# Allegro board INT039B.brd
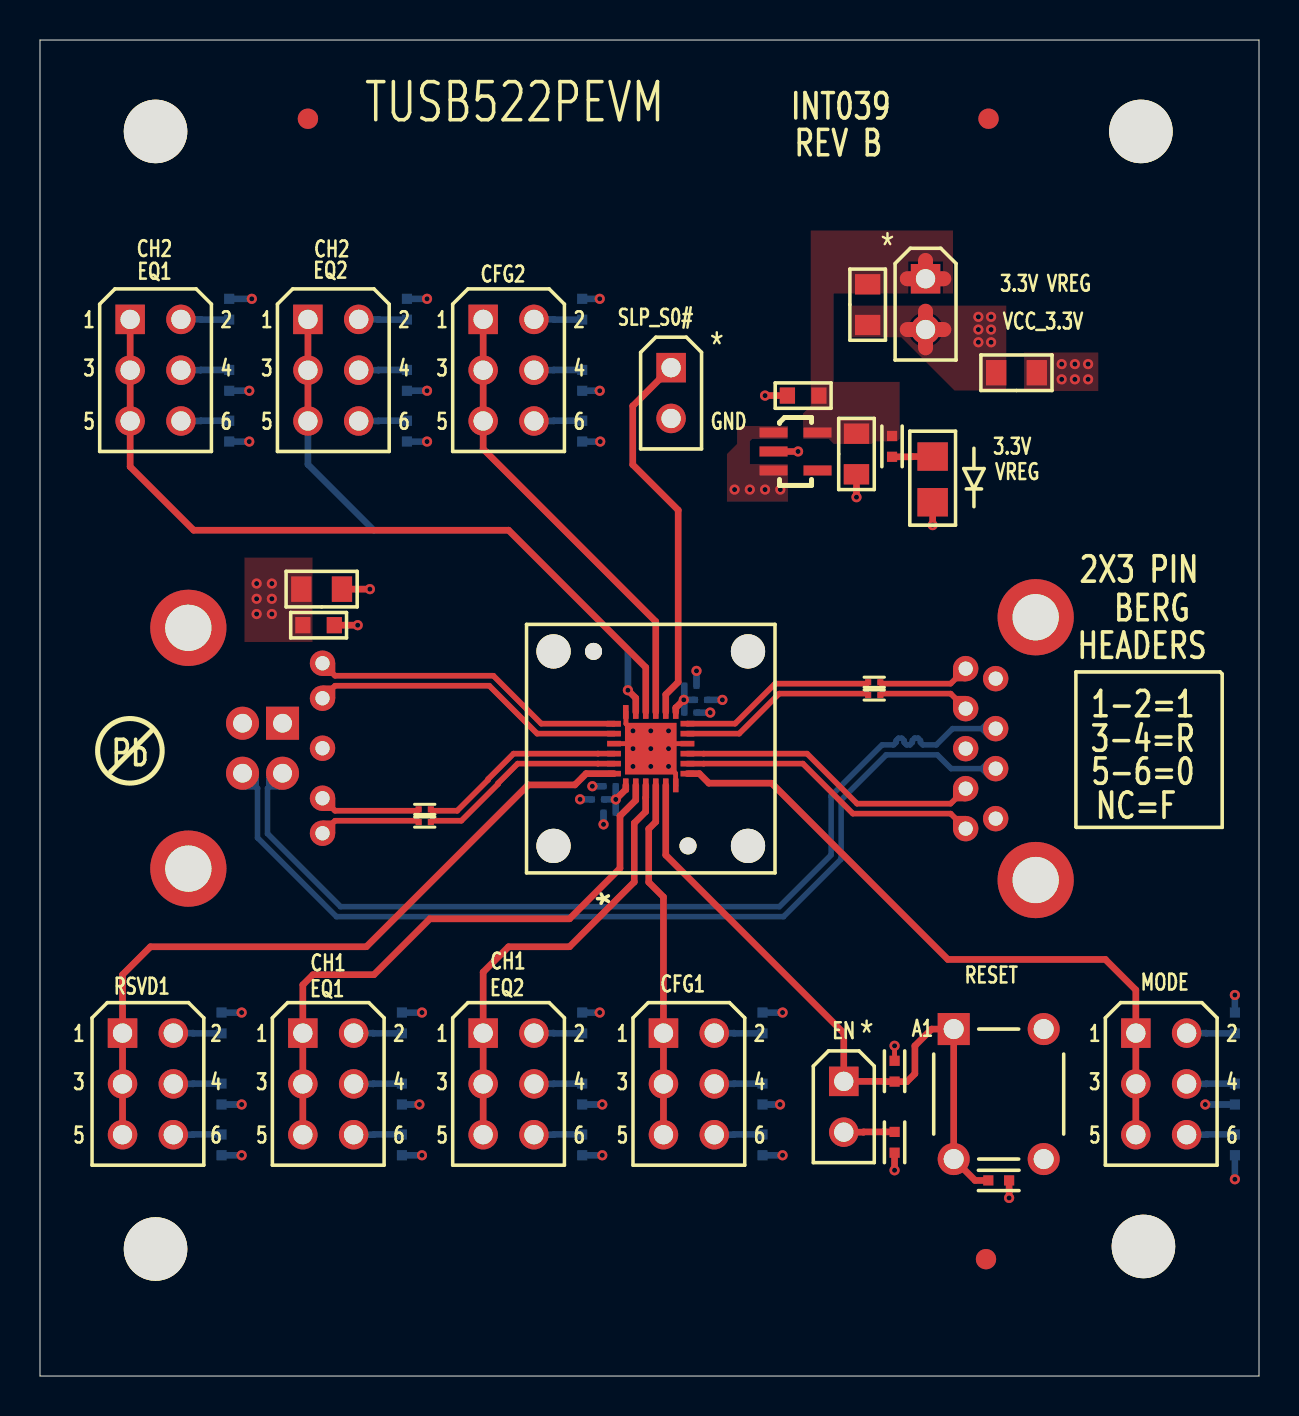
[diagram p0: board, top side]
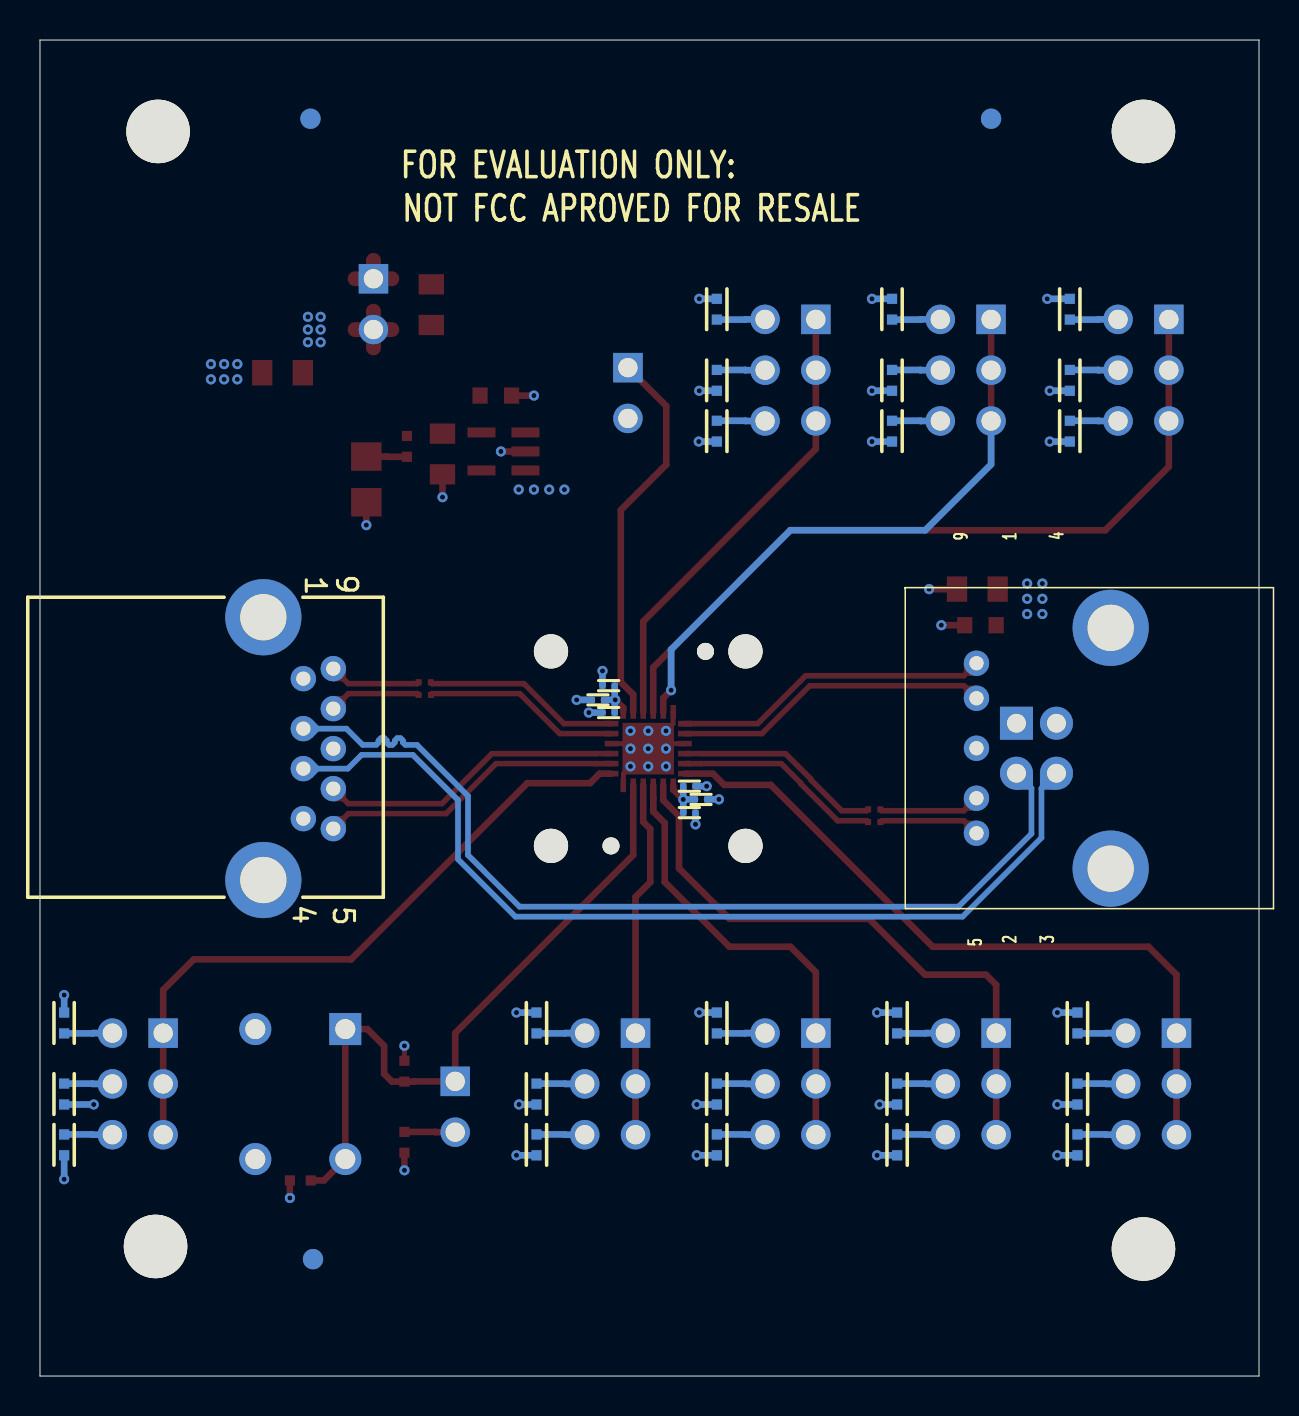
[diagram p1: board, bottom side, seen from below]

Outline 60.96 x 66.8 mm; copper layers: TOP, L2_GND, L3_PWR, BOTTOM. Coordinates in mm from the lower left corner of the outline.
Outline path: 0,66.8 60.96,66.8 60.96,0 0,0 0,66.8

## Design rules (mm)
net group DIFFPAIR0: nets TX1N_CONN TX1P_CONN
net group DIFFPAIR1: nets RX2N RX2P
net group DIFFPAIR2: nets USB2_DM USB2_DP
net group DIFFPAIR3: nets RX1N RX1P
net group DIFFPAIR4: nets TX2N_CONN TX2P_CONN
net group DIFFPAIR5: nets TX1N TX1P
net group DIFFPAIR6: nets TX2N TX2P

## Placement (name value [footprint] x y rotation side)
C1  0.1uF  [0201]  19.24 28.33 0 top
C2  0.1uF  [0201]  19.24 27.7 0 top
C3  0.1uF  [0201]  41.72 34.69 0 top
C4  0.1uF  [0201]  41.72 34.05 0 top
C5  10uF  [0805]  14.08 39.34 0 top
C6  10uF  [0805]  40.83 46.1 270 top
C7  1uf  [0603]  13.93 37.54 0 top
C8  1uf  [0603]  38.16 49.02 180 top
C9  1uF  [0201]  28.49 29.49 180 bottom
C10  1uF  [0201]  32.52 33.17 0 bottom
C11  0.1uF  [0201]  27.9 28.83 180 bottom
C12  0.1uF  [0201]  33.06 33.81 0 bottom
C13  0.01uF  [0201]  28.49 28.17 180 bottom
C14  0.01uF  [0201]  32.52 34.52 0 bottom
C15  22uF  [0805]  48.83 50.16 0 top
C16  200nF  [0402]  47.94 9.78 0 top
D1  LED Green 0805  [LED_0805]  44.64 44.83 90 top
J1  HDR3X2 .1X.1  [HDR_THVT_2X3_100]  13.14 17.14 0 top
J2  HDR3X2 .1X.1  [HDR_THVT_2X3_100]  22.16 17.14 0 top
J3  HDR3X2 .1X.1  [HDR_THVT_2X3_100]  4.51 52.83 0 top
J4  HDR3X2 .1X.1  [HDR_THVT_2X3_100]  13.4 52.83 0 top
J5  HDR3X2 .1X.1  [HDR_THVT_2X3_100]  31.18 17.14 0 top
J6  HDR3X2 .1X.1  [HDR_THVT_2X3_100]  4.13 17.14 0 top
J7  HDR3X2 .1X.1  [HDR_THVT_2X3_100]  54.8 17.14 0 top
J8  HDR3X2 .1X.1  [HDR_THVT_2X3_100]  22.16 52.83 0 top
J9  HDR2X1 M .1  [HDR_THVT_1X2_100]  40.2 14.73 0 top
J10  HDR2X1 M .1  [HDR_THVT_1X2_100]  31.56 50.42 0 top
J11  HDR2X1 M .1  [HDR_THVT_1X2_100]  44.28 54.86 0 top
NOREF  -  []  88.33 38.1 0 top
NOREF#2  -  []  12.05 0.86 0 top
NOREF#3  -  [unnamed#2]  55.18 6.48 0 top
NOREF#4  -  [unnamed#2]  5.78 6.35 0 top
NOREF#5  -  []  -0.57 0 0 top
NOREF#6  -  [unnamed#2]  13.4 62.87 0 top
NOREF#7  -  [unnamed#2]  47.43 62.87 0 top
NOREF#8  -  [unnamed#2]  55.05 62.23 0 top
NOREF#9  -  []  60.96 0 90 top
NOREF#10  -  []  -4.38 -69.85 0 top
NOREF#11  -  []  0 66.8 0 top
NOREF#12  -  [unnamed#2]  47.31 5.84 0 top
NOREF#13  -  [unnamed#2]  5.78 62.23 0 top
NOREF#14  -  []  29.92 5.29 180 bottom
NOREF#15  -  [unnamed#2]  47.43 62.87 180 bottom
NOREF#16  -  [unnamed#2]  47.31 5.84 180 bottom
NOREF#17  -  [unnamed#2]  13.4 62.87 180 bottom
P1  USB3.0 Type B Receptacle  [USB3_TYPEB_AK4AA009]  12.13 32.64 90 bottom
P2  USB3 Type A Receptacle  [USB3_TYPEA]  46.29 31.37 270 bottom
R1  1k  [0402]  18.1 17.65 90 bottom
R2  20k  [0402]  18.1 14.1 270 bottom
R3  1k  [0402]  18.1 11.56 270 bottom
R4  1k  [0402]  27.11 17.65 90 bottom
R5  20k  [0402]  27.11 14.1 270 bottom
R6  1k  [0402]  27.11 11.56 270 bottom
R7  1k  [0402]  9.46 53.34 90 bottom
R8  20k  [0402]  9.46 49.78 270 bottom
R9  1k  [0402]  9.46 47.24 270 bottom
R10  1k  [0402]  18.35 53.34 90 bottom
R11  20k  [0402]  18.35 49.78 270 bottom
R12  1k  [0402]  18.35 47.24 270 bottom
R13  1k  [0402]  36.13 17.65 90 bottom
R14  20k  [0402]  36.13 14.1 270 bottom
R15  1k  [0402]  36.13 11.56 270 bottom
R16  1k  [0402]  9.08 17.65 90 bottom
R17  20k  [0402]  9.08 14.1 270 bottom
R18  1k  [0402]  9.08 11.56 270 bottom
R19  1k  [0402]  59.75 17.65 90 bottom
R20  20k  [0402]  59.75 14.1 270 bottom
R21  1k  [0402]  59.75 11.56 270 bottom
R22  1k  [0402]  27.11 53.34 90 bottom
R23  20k  [0402]  27.11 49.78 270 bottom
R24  1k  [0402]  27.11 47.24 270 bottom
R25  1k  [0402]  42.74 11.68 270 top
R26  0 Ohm  [0805]  41.39 53.57 270 top
R27  10k - NO POP  [0402]  42.74 15.24 270 top
R28  300 Ohm  [0402]  42.61 46.48 270 top
SW1  Switch - Push Button  [SW_THVT_EVQPAX05]  47.94 14.1 0 top
U1  TUSB1002RGE  [SKT_TUSB1002RGE]  30.54 31.37 90 top
U2  LP5907  [DBV_R-PDSO-G5]  37.78 46.23 0 top

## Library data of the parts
C1-C4 C9-C14 = cc0201
C5 C6 C15 = cc0805
C7 C8 = cc0603 1.0uf 25V
C16 = cc0402
D1 = LED Green 0805_0
J1-J8 = HDR3X2 M .1X.1
J9-J11 = HDR2X1 M .1
P1 = USB 3.0 Type B Receptacle
P2 = USB 3.0 Type A Receptacle
R1-R25 R27 R28 = r0402
R26 = r0805
SW1 = Switch - Push Button_0
U1 = TUSB1002RGE
U2 = LP5907

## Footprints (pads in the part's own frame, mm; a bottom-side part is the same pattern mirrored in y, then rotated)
0201
  rect 0.305x0.305 smd: 1(-0.305,0) 2(0.305,0)
0402
  rect 0.508x0.508 smd: 1(-0.521,0) 2(0.521,0)
0603
  rect 0.762x0.813 smd: 1(-0.787,0) 2(0.787,0)
0805
  rect 1.016x1.27 smd: 1(-1.016,0) 2(1.016,0)
DBV_R-PDSO-G5
  rect 1.4x0.5 smd: 1(-1.1,0.95) 2(-1.1,0) 3(-1.1,-0.95) 4(1.1,-0.95) 5(1.1,0.95)
HDR_THVT_1X2_100
  rect 1.473x1.473 hole 0.965: 1(0,0)
  round 1.473 hole 0.965: 2(0,-2.54)
HDR_THVT_2X3_100
  rect 1.473x1.473 hole 0.965: 1(0,0)
  round 1.473 hole 0.965: 2(2.54,0) 3(0,-2.54) 4(2.54,-2.54) 5(0,-5.08) 6(2.54,-5.08)
LED_0805
  rect 1.422x1.524 smd: 1(-1.143,0) 2(1.143,0)
SKT_TUSB1002RGE
  round 1.71 hole 1.71 unplated: (-4.863,4.863) (-4.863,-4.863) (4.863,4.863) (4.863,-4.863)
  round 0.85 hole 0.85 unplated: (-4.863,-1.863) (4.863,2.863)
  rect 0.69x0.28 smd: 1(-1.835,1.25) 2(-1.835,0.75) 3(-1.835,0.25) 4(-1.835,-0.25) 5(-1.835,-0.75) 6(-1.835,-1.25) 13(1.835,-1.25) 14(1.835,-0.75) 15(1.835,-0.25) 16(1.835,0.25) 17(1.835,0.75) 18(1.835,1.25)
  rect 0.28x0.69 smd: 7(-1.25,-1.835) 8(-0.75,-1.835) 9(-0.25,-1.835) 10(0.25,-1.835) 11(0.75,-1.835) 12(1.25,-1.835) 19(1.25,1.835) 20(0.75,1.835) 21(0.25,1.835) 22(-0.25,1.835) 23(-0.75,1.835) 24(-1.25,1.835)
  rect 2.58x2.58 smd: 25(0,0)
SW_THVT_EVQPAX05
  rect 1.6x1.6 hole 1: A1(-2.25,3.25)
  round 1.6 hole 1: A2(-2.25,-3.25) B1(2.25,3.25) B2(2.25,-3.25)
unnamed#2
  round 3.175 hole 3.175 unplated: (0,0)
USB3_TYPEA
  round 1.27 hole 0.711: 1(-3.5,-1.5) 2(-1,-1.5) 3(1,-1.5) 4(3.5,-1.5) 5(4,0) 6(2,0) 7(0,0) 8(-2,0) 9(-4,0)
  round 3.81 hole 2.311: 10(-6.57,-3.5) 11(6.57,-3.5)
USB3_TYPEB_AK4AA009
  rect 1.651x1.651 hole 0.94: 1(0,0)
  round 1.651 hole 0.94: 2(-2.5,0) 3(-2.5,-2) 4(0,-2)
  round 1.27 hole 0.711: 5(-5.5,2) 6(-3.75,2) 7(-1.25,2) 8(1.25,2) 9(3,2)
  round 3.81 hole 2.311: 10(-7.27,-4.71) 11(4.77,-4.71)

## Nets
3.3V: C6.1 C8.1 J11.1 R26.1 R28.1 U2.5(VOUT)
GND: C5.2 C6.2 C7.2 C8.2 C9.2 C10.2 C11.2 C12.2 C13.2 C14.2 C15.2 C16.2 D1.1(CATHODE) J10.2 P1.4(GND) P1.7(GND_DRAIN) P1.10(SHIELD1) P1.11(SHIELD2) P2.4(GND) P2.7(GND_DRAIN) P2.10(SHIELD1) P2.11(SHIELD2) R2.2 R3.2 R5.2 R6.2 R8.2 R9.2 R11.2 R12.2 R14.2 R15.2 R17.2 R18.2 R20.2 R21.2 R23.2 R24.2 R25.2 SW1.B1 SW1.B2 U1.6(GND#6) U1.10(GND#10) U1.18(GND#18) U1.21(GND#21) U1.25(PAD) U2.2(GND)
VBUS: C5.1 C7.1 P1.1(VBUS) P2.1(VBUS) U2.1(VIN) U2.3(EN)
VCC_3.3V: C9.1 C10.1 C11.1 C12.1 C13.1 C14.1 C15.1 J11.2 R1.2 R4.2 R7.2 R10.2 R13.2 R16.2 R19.2 R22.2 R26.2 R27.1 U1.1(VCC#1) U1.13(VCC#13)
CH1_CFG1: J1.1 J1.3 J1.5 U1.2(CH1_CFG1)
CH1_CFG2: J2.1 J2.3 J2.5 U1.3(CH1_CFG2)
CH2_CFG1: J3.1 J3.3 J3.5 U1.16(CH2_CFG1)
CH2_CFG2: J4.1 J4.3 J4.5 U1.17(CH2_CFG2)
EN_RXD: C16.1 J9.1 R27.2 SW1.A1 SW1.A2 U1.5(EN_RXD)
RSVD1: J10.1 U1.14(RSVD1)
RX1N: P2.5(SS_RX_N) U1.8(RX1N)
RX1P: P2.6(SS_RX_P) U1.9(RX1P)
RX2N: P1.8(SS_RX_N) U1.20(RX2N)
RX2P: P1.9(SS_RX_P) U1.19(RX2P)
SQL_CFG: J8.1 J8.3 J8.5 U1.15(SQL_CFG)
TEST1: J5.1 J5.3 J5.5 U1.4(TEST1)
TEST2: J7.1 J7.3 J7.5 U1.7(TEST2)
TEST3: J6.1 J6.3 J6.5 U1.24(TEST3)
TX1N: C2.2 U1.23(TX1N)
TX1N_CONN: C2.1 P1.5(SS_TX_N)
TX1P: C1.2 U1.22(TX1P)
TX1P_CONN: C1.1 P1.6(SS_TX_P)
TX2N: C4.1 U1.11(TX2N)
TX2N_CONN: C4.2 P2.8(SS_TX_N)
TX2P: C3.1 U1.12(TX2P)
TX2P_CONN: C3.2 P2.9(SS_TX_P)
USB2_DM: P1.2(USB2_DM) P2.2(USB2_DM)
USB2_DP: P1.3(USB2_DP) P2.3(USB2_DP)
N04057: J1.2 R1.1
N04069: J1.4 R2.1
N04073: J1.6 R3.1
N04156: J2.2 R4.1
N04168: J2.4 R5.1
N04172: J2.6 R6.1
N04339: J3.2 R7.1
N04351: J3.4 R8.1
N04355: J3.6 R9.1
N04442: J4.2 R10.1
N04460: J4.4 R11.1
N04464: J4.6 R12.1
N04816: J5.2 R13.1
N04828: J5.4 R14.1
N04832: J5.6 R15.1
N05035: J7.2 R19.1
N05047: J7.4 R20.1
N05051: J7.6 R21.1
N05588: J6.2 R16.1
N05600: J6.4 R17.1
N05604: J6.6 R18.1
N05749: J8.2 R22.1
N05761: J8.4 R23.1
N05765: J8.6 R24.1
N05896: J9.2 R25.1
N16532433: D1.2(ANNODE) R28.2

Pads without a net: U2 4

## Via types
v1: diameter 0.508, hole 0.254, TOP to BOTTOM, 73 vias

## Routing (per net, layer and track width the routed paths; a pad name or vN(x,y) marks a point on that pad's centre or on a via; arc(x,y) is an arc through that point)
3.3V: length 2.7
  TOP w0.749: J11.1 45.2,54.86 ; J11.1 43.37,54.86 ; J11.1 44.28,55.78
GND: length 94.1
  TOP w0.241: 30.29,31.62 v1(30.54,31.37) ; 30.29,31.62 v1(29.65,32.26) 29.3,32.61 29.3,33.2 U1.18 ; 30.29,31.62 U1.21 ; v1(30.54,31.37) v1(31.43,30.48) 31.79,30.13 31.79,29.54 U1.6 ; v1(30.54,31.37) 30.79,31.62 U1.10
  TOP w0.33: C8.2 v1(36.26,49.02) ; C6.2 v1(40.83,43.94) ; R25.2 v1(42.74,10.29) ; U2.2 v1(37.91,46.23) ; C5.2 v1(16.5,39.34) ; C16.2 v1(48.46,8.9) ; C7.2 v1(15.89,37.54) ; D1.1 v1(44.64,42.55)
  L2_GND w0.241: SW1.B1 50.19,18.33 ; SW1.B1 49.21,17.35 ; SW1.B1 50.19,16.37 ; SW1.B1 51.17,17.35 ; 49.21,10.85 SW1.B2 ; SW1.B2 50.19,9.87 ; SW1.B2 50.19,11.83 ; SW1.B2 51.17,10.85 ; 7.42,23.29 P1.10 ; P1.10 7.42,27.45 ; P1.10 9.5,25.37 ; P1.10 5.34,25.37 ; 10.13,31.64 P1.4 ; P1.4 9.12,32.64 ; P1.4 10.13,33.64 ; P2.10 49.79,40.02 ; P2.10 51.87,37.94 ; P2.10 47.71,37.94 ; P2.10 49.79,35.86 ; P1.11 7.42,39.49 ; P1.11 5.34,37.41 ; P1.11 7.42,35.33 ; P1.11 9.5,37.41 ; P1.7 14.94,31.39 ; P1.7 14.13,30.58 ; P1.7 13.32,31.39 ; P1.7 14.13,32.2 ; J10.2 32.47,47.88 ; J10.2 31.56,46.96 ; J10.2 30.64,47.88 ; J10.2 31.56,48.79 ; P2.7 47.1,31.37 ; P2.7 46.29,30.56 ; P2.7 45.48,31.37 ; P2.7 46.29,32.18 ; P2.11 49.79,26.88 ; P2.11 49.79,22.72 ; P2.11 47.71,24.8 ; P2.11 51.87,24.8 ; P2.4 47.79,28.68 ; P2.4 47.79,27.06 ; P2.4 48.6,27.87
  BOTTOM w0.33: R15.2 v1(37.13,11.04) ; R23.2 v1(27.99,49.26) ; C10.2 v1(33.52,33.17) ; R9.2 v1(10.46,46.72) ; R8.2 v1(10.46,49.26) ; R14.2 v1(37.01,13.58) ; C11.2 v1(27.01,28.83) ; R20.2 v1(58.27,13.58) ; R5.2 v1(28.12,13.58) ; R11.2 v1(19.35,49.26) ; R17.2 v1(10.08,13.58) ; C9.2 v1(27.62,29.49) ; R3.2 v1(19.1,11.04) ; C13.2 v1(28.18,27.58) ; R12.2 v1(19.35,46.72) ; C14.2 v1(32.83,35.26) ; R18.2 v1(10.08,11.04) ; R24.2 v1(28.02,46.72) ; R21.2 v1(59.75,9.84) ; R6.2 v1(28.12,11.04) ; R2.2 v1(18.97,13.58) ; C12.2 v1(34.12,33.81)
  vias: v1(29.65,31.37) v1(29.65,30.48) v1(30.54,32.26) v1(30.54,30.48) v1(31.43,32.26) v1(31.43,31.37) v1(51.09,50.6) v1(51.09,49.83) v1(51.75,50.6) v1(51.75,49.83) v1(52.41,50.6) v1(52.41,49.83)
VBUS: length 5.5
  L3_PWR w0.241: P1.1 12.13,33.64 ; P1.1 12.13,31.64 ; P1.1 13.13,32.64 ; P2.1 47.79,35.68 ; P2.1 48.6,34.87 ; P2.1 47.79,34.06
  vias: v1(10.83,39.62) v1(10.83,38.86) v1(10.83,38.1) v1(11.6,39.62) v1(11.6,38.86) v1(11.6,38.1) v1(34.73,44.32) v1(35.5,44.32) v1(36.26,44.32) v1(37.02,44.32)
VCC_3.3V: length 21.4
  TOP w0.241: R27.1 v1(42.74,16.51)
  TOP w0.33: v1(28.79,28.83) 29.29,29.33 U1.1 ; U1.13 31.79,33.41 v1(32.19,33.81)
  TOP w0.749: J11.2 45.2,52.32 ; J11.2 44.28,51.41 ; J11.2 43.37,52.32 ; J11.2 44.28,53.24
  L3_PWR w0.749: 44.28,51.41 J11.2 ; J11.2 45.2,52.32 ; J11.2 43.37,52.32 ; J11.2 44.28,53.24
  BOTTOM w0.241: 32.2,33.81 v1(32.19,33.81)
  BOTTOM w0.33: R16.2 v1(10.08,18.17) ; C13.1 28.79,28.83 v1(28.79,28.83) ; R4.2 v1(27.99,18.17) ; R10.2 v1(19.35,53.86) ; v1(32.19,33.81) 32.22,33.84 C14.1 ; R1.2 v1(19.1,18.17) ; R19.2 v1(59.75,19.05) ; v1(28.79,28.83) C11.1 ; v1(28.79,28.83) 28.79,28.83 C9.1 ; R13.2 v1(37.13,18.17) ; R7.2 v1(10.59,53.86) ; C12.1 32.2,33.81 32.22,33.78 C10.1 ; R22.2 v1(27.99,53.86)
  vias: v1(46.93,52.96) v1(46.93,52.32) v1(46.93,51.69) v1(47.56,52.96) v1(47.56,52.32) v1(47.56,51.69)
CH1_CFG1: length 30.2
  TOP w0.33: J1.5 J1.3 J1.1 13.14,19.56 13.65,20.07 16.7,20.07 19.49,22.86 26.48,22.86 29,25.38 29,28 29.79,28.79 U1.2
CH1_CFG2: length 22.6
  TOP w0.33: U1.3 30.29,28.92 30.29,28.92 30.29,28.22 29.72,27.65 29.72,24.7 26.48,21.46 23.43,21.46 22.16,20.19 J2.1 J2.3 J2.5
CH2_CFG1: length 39.5
  TOP w0.33: J3.1 J3.3 J3.5 4.51,45.47 7.68,42.29 23.43,42.29 30.29,35.43 U1.16
CH2_CFG2: length 30.4
  TOP w0.33: v1(29.4,34.29) 29.79,33.9 U1.17 ; J4.5 J4.3 J4.1
  BOTTOM w0.33: v1(29.4,34.29) 29.4,36.32 23.43,42.29 16.69,42.29 13.4,45.58 J4.5
EN_RXD: length 34.6
  TOP w0.33: C16.1 46.76,9.78 SW1.A2 SW1.A1 44.59,17.35 43.75,16.51 43.75,15.11 43.36,14.72 R27.2 42.23,14.72 42.22,14.73 J9.1 40.2,17.14 31.29,26.05 U1.5
RSVD1: length 19.2
  TOP w0.33: U1.14 31.29,34.07 31.92,34.7 31.92,43.3 29.64,45.57 29.64,48.5 J10.1
RX1N: length 15.3
  TOP w0.279: P2.5 45.54,28.12 40.65,28.12 38.15,30.62 33.19,30.62 33.19,30.62 U1.8
RX1P: length 15.3
  TOP w0.279: U1.9 33.19,31.12 33.19,31.12 38.36,31.12 40.86,28.62 45.54,28.62 P2.6
RX2N: length 15.8
  TOP w0.279: P1.8 14.75,34.51 22.47,34.51 24.86,32.12 U1.20
RX2P: length 15.8
  TOP w0.279: P1.9 14.75,35.01 22.67,35.01 25.07,32.62 U1.19
SQL_CFG: length 23.2
  TOP w0.33: U1.15 30.79,37.72 22.16,46.35 J8.5 J8.3 J8.1
TEST1: length 17.9
  TOP w0.33: J5.5 J5.3 J5.1 31.18,23.95 30.44,24.69 30.44,27.36 30.79,27.71 U1.4
TEST2: length 34.1
  TOP w0.33: U1.7 32.97,30.12 33.45,29.64 36.59,29.64 45.4,20.83 53.28,20.83 54.8,19.3 J7.1 J7.3 J7.5
TEST3: length 36.7
  TOP w0.33: U1.24 27.31,30.12 26.75,29.56 24.41,29.56 16.32,21.46 5.52,21.46 4.13,20.07 J6.1 J6.3 J6.5
TX1N: length 10.4
  TOP w0.279: U1.23 27.9,30.62 27.9,30.62 23.89,30.62 22.91,29.64 22.91,29.6 21.07,27.76 19.61,27.76 C2.2
TX1N_CONN: length 5.1
  TOP w0.279: P1.5 14.75,27.76 18.87,27.76 C2.1
TX1P: length 10.4
  TOP w0.279: U1.22 27.9,31.12 27.9,31.12 23.68,31.12 22.41,29.85 22.41,29.81 20.86,28.26 19.61,28.26 C1.2
TX1P_CONN: length 5.1
  TOP w0.279: C1.1 18.87,28.26 14.75,28.26 P1.6
TX2N: length 9.9
  TOP w0.279: U1.11 34.97,32.12 36.97,34.12 41.35,34.12 C4.1
TX2N_CONN: length 4.6
  TOP w0.279: C4.2 42.09,34.12 45.54,34.12 P2.8
TX2P: length 9.9
  TOP w0.279: C3.1 41.35,34.62 36.76,34.62 34.76,32.62 U1.12
TX2P_CONN: length 4.6
  TOP w0.279: P2.9 45.54,34.62 42.09,34.62 C3.2
USB2_DM: length 47.5
  BOTTOM w0.279: P2.2 45.64,32.37 44.82,31.56 44.15,31.56 44.03,31.68 44.03,31.77 43.91,31.89 43.74,31.89 43.62,31.77 43.62,31.68 43.5,31.56 43.34,31.56 43.22,31.68 43.22,31.77 43.1,31.89 42.93,31.89 42.81,31.77 42.81,31.68 42.69,31.56 42.11,31.56 39.56,29.01 39.56,26.05 36.98,23.47 15.03,23.47 11.38,27.12 11.38,29.39 P1.2
USB2_DP: length 47.5
  BOTTOM w0.279: P1.3 10.88,29.39 10.88,26.91 14.82,22.97 37.18,22.97 40.06,25.84 40.06,28.8 42.32,31.06 44.87,31.06 45.56,30.37 P2.3
N04057: length 2.4
  BOTTOM w0.33: R1.1 16.68,17.13 16.67,17.14 J1.2
N04069: length 2.4
  BOTTOM w0.33: R2.1 16.68,14.62 16.67,14.61 J1.4
N04073: length 2.4
  BOTTOM w0.33: J1.6 16.67,12.06 16.68,12.08 R3.1
N04156: length 2.4
  BOTTOM w0.33: J2.2 25.69,17.14 25.7,17.13 R4.1
N04168: length 2.4
  BOTTOM w0.33: J2.4 25.69,14.61 25.7,14.62 R5.1
N04172: length 2.4
  BOTTOM w0.33: J2.6 25.69,12.06 25.7,12.08 R6.1
N04339: length 2.4
  BOTTOM w0.33: R7.1 8.05,52.82 8.03,52.83 J3.2
N04351: length 2.4
  BOTTOM w0.33: J3.4 8.03,50.29 8.05,50.3 R8.1
N04355: length 2.4
  BOTTOM w0.33: J3.6 8.03,47.75 8.05,47.76 R9.1
N04442: length 2.4
  BOTTOM w0.33: R10.1 16.94,52.82 16.92,52.83 J4.2
N04460: length 2.4
  BOTTOM w0.33: R11.1 16.94,50.3 16.92,50.29 J4.4
N04464: length 2.4
  BOTTOM w0.33: J4.6 16.92,47.75 16.94,47.76 R12.1
N04816: length 2.4
  BOTTOM w0.33: R13.1 34.72,17.13 34.7,17.14 J5.2
N04828: length 2.4
  BOTTOM w0.33: J5.4 34.7,14.61 34.72,14.62 R14.1
N04832: length 2.4
  BOTTOM w0.33: R15.1 34.72,12.08 34.7,12.06 J5.6
N05035: length 2.4
  BOTTOM w0.33: R19.1 58.34,17.13 58.33,17.14 J7.2
N05047: length 2.4
  BOTTOM w0.33: R20.1 58.34,14.62 58.33,14.61 J7.4
N05051: length 2.4
  BOTTOM w0.33: R21.1 58.34,12.08 58.33,12.06 J7.6
N05588: length 2.4
  BOTTOM w0.33: R16.1 7.66,17.13 7.65,17.14 J6.2
N05600: length 2.4
  BOTTOM w0.33: R17.1 7.66,14.62 7.65,14.61 J6.4
N05604: length 2.4
  BOTTOM w0.33: R18.1 7.66,12.08 7.65,12.06 J6.6
N05749: length 2.4
  BOTTOM w0.33: R22.1 25.7,52.82 25.69,52.83 J8.2
N05761: length 2.4
  BOTTOM w0.33: J8.4 25.69,50.29 25.7,50.3 R23.1
N05765: length 2.4
  BOTTOM w0.33: R24.1 25.7,47.76 25.69,47.75 J8.6
N05896: length 2.5
  TOP w0.33: J9.2 41.18,12.19 41.19,12.2 R25.1
N16532433: length 2
  TOP w0.33: R28.2 43.62,45.96 43.63,45.97 D1.2

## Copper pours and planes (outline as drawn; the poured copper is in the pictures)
3.3V on TOP: 42.86,46.74 41.72,46.74 41.59,46.61 39.69,46.61 39.43,46.86 38.16,46.86 38.16,48.13 38.54,48.51 38.54,57.28 45.66,57.28 45.66,54.13 39.69,54.13 39.69,49.71 42.99,49.71 42.99,46.86
GND on TOP: 49.21,51.18 49.21,49.25 52.92,49.25 52.92,51.18
GND on L2_GND: 60.35,0.64 0.63,0.64 0.63,66.17 60.34,66.17
VBUS on TOP: 37.4,47.5 37.4,46.86 35.62,46.86 35.5,46.74 35.5,45.59 37.4,45.59 37.4,43.71 34.35,43.71 34.35,46.1 34.86,46.61 34.86,47.5
VBUS on TOP: 13.63,40.92 13.63,36.7 10.22,36.7 10.22,40.92
VBUS on L3_PWR: 10.35,31.5 10.35,45.72 49.21,45.72 49.21,33.66 45.66,33.66 45.66,42.67 13.53,42.67 13.53,31.5
VCC_3.3V on TOP: 40.58,53.52 48.32,53.52 48.32,49.28 45.73,49.28 43.07,51.94 40.58,51.94
VCC_3.3V on L3_PWR: 60.33,0.63 56.36,0.64 0.63,0.64 0.63,66.17 60.34,66.17

Small or netless copper shapes (teardrops, artwork), in the pictures only: 9 on TOP, 4 on BOTTOM

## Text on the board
BOTTOM: LAYER 4 - BOTTOM SIDE
Board Geometry/Soldermask Bottom: SOLDERMASK BOTTOM
Package Geometry/Pastemask Bottom: PASTEMASK BOTTOM
Ref Des/Silkscreen Bottom: NOT FCC APROVED FOR RESALE | FOR EVALUATION ONLY: | SILKSCREEN BOTTOM
TOP: LAYER 1 - TOP SIDE
Board Geometry/Soldermask Top: SOLDERMASK TOP
Package Geometry/Pastemask Top: PASTEMASK TOP
Ref Des/Silkscreen Top: 1 | 3 | 5 | RSVD1 | CH2 | EQ1 | 2 | 4 | 6 | CH1 | EQ2 | CFG2 | SLP_S0# | CFG1 | GND | EN | RESET | 3.3V | VREG | 3.3V VREG | VCC_3.3V | MODE | Pb | INT039 | REV B | HEADERS | 2X3 PIN | 3-4=R | 1-2=1 | 5-6=0 | NC=F | BERG | SILKSCREEN TOP | TUSB522PEVM
L2_GND: LAYER 2 - GND PLANE
L3_PWR: LAYER 3 - PWR PLANE
XSECTION_CHART: * AIR 0 MIL | * SOLDERMASK-0.8MIL 0.8 MIL | L1: COPPER_1/2OZ_PLATED 1.4 MIL | * FILL_0.200 7.87 MIL | L2: COPPER_1.0OZ 1.4 MIL | * CORE_1.00 39.37 MIL | L3: COPPER_1.0OZ 1.4 MIL | L4: COPPER_1/2OZ_PLATED 1.4 MIL | DESIGN CROSS SECTION CHART | ___________________________ | TOTAL THICKNESS 62.31 MIL | 1-4
DIMENSION: FABRICATION DRAWING | CAD ORIGIN
User.6: LAYER 1 | LAYER 2 | LAYER 3 | LAYER 4 | LAYER | NO. | TABLE 1: | TOP | L2_GND | L3_PWR | BOTTOM | NAME | DIFFIRENTIAL PAIR | IMPEDANCE (OHMS) | 90  +/- 10% | DIFF TRACE | WIDTH | 0.011" | SPACING | 0.00866" | SINGLE ENDED | 50 +/- 10% | TRACE WIDTH | 0.013" | REFERENCE | SPECIAL FAB NOTES: | PLACE DRILL CHART HERE: | 1:FAB SHOP MUST FOLLOW THE SOLDER MASK REVIEW LAYERS. | 2:ALL BOARDS MUST MEET OR EXCEED UL94-V0 REQUIREMENTS | 3:Place Caps C5 and C7 closer to connector P1. | 4:Place Caps C6 and C8 close to U2 | 5:Place Caps C9, C11, C13 underneath U1, close to pin 1. | 6:Place Caps C10, C12, C14 underneath U1, close to pin 13. | MIN. ANNULAR RING 2 MIL EXTERNAL PER IPC-6012C CLASS 2 | REGISTRATION TOLERANCES: METAL +/- X MIL,HOLES +/- X MIL | IMPEDANCE CONTROL: | BOARD SIZE (REFER ALSO ARRAY/PANEL PROFILING INFORMATION) | MIXED DIELECTRIC: | LAMINATE MATERIAL: | THICKNESS: | TOLERANCE: | COPPER THICKNESS (FINISHED): | BOARD FINISH: | NUMBER OF LAYERS: | MIN. TRACK WIDTH: | MIN. CLEARANCE  : | MIN. VIA PAD/DRILL: | THIEVING ALLOWED: | X | OUTER: | INNER SIGNAL: | INNER PLANE: | OTHER: | SILKSCREEN: | SOLDERMASK: (PER IPC-6011,6012) | BOARD SURFACE TREATMENT: | ADDITIONAL REQUIREMENTS: | VENDOR MARKING: | SILKSCREEN COLOR: | SOLDERMASK COLOR: | THROUGH-HOLE VIA TREATMENT: | VIA FILL USING NON-CONDUCTIVE EPOXY: | FOR WIRE BONDING: | VENDOR DATE CODE,UL,LOGO: | FR-4 HIGH Tg | 0.062" +/-10% | IPC-6012C TYPE 3 CLASS 2 | OTHER +/- | MICRO-SECTION | CERTIFICATES OF COMPLIANCE | NICKEL/GOLD (ENIG) | IMMERSION TIN | HARD GOLD | IN AN OPEN AREA | 1/4 OZ. | OPEN | NO | 4 | 11 MIL | 8.66 MIL | 20/10 MIL | NONE | DESIGN INFORMATION | ROGERS 4350B | 0.093" +/-10% | YES | TDR REPORTS/COUPONS | WHITE | GREEN | SOFT GOLD | TENTED | 1/2 OZ. | BOW & TWIST: | ORGANIC (OSP) | OTHER | WHERE INDICATED (SEE DRAWING) | YES - SEE TABLE 1 | ETCH | IDENTIFIER: | BLUE | RoHS | 1.0 OZ. | SILKSCREEN | PER SUPPLIED ARTWORK | ALL x MIL VIAS | ELECTRICAL TEST | UL 94V-0 | HASL | 2.0 OZ. | BREAK-AWAY | ENEPIG
User.10: FIGURE | SIZE | 91.0 | 39.37 | 38.0 | 37.0 | 28.0 | 10.0 | 125.0 | 67.32 | 33.46 | DRILL CHART: TOP to BOTTOM | ALL UNITS ARE IN MILS | TOLERANCE | +3.0/-3.0 | +39.37/-0.0 | +2.0/-2.0 | +3.94/-3.94 | +1.97/-1.97 | PLATED | NON-PLATED | QTY | 4 | 54 | 14 | 75 | 2
